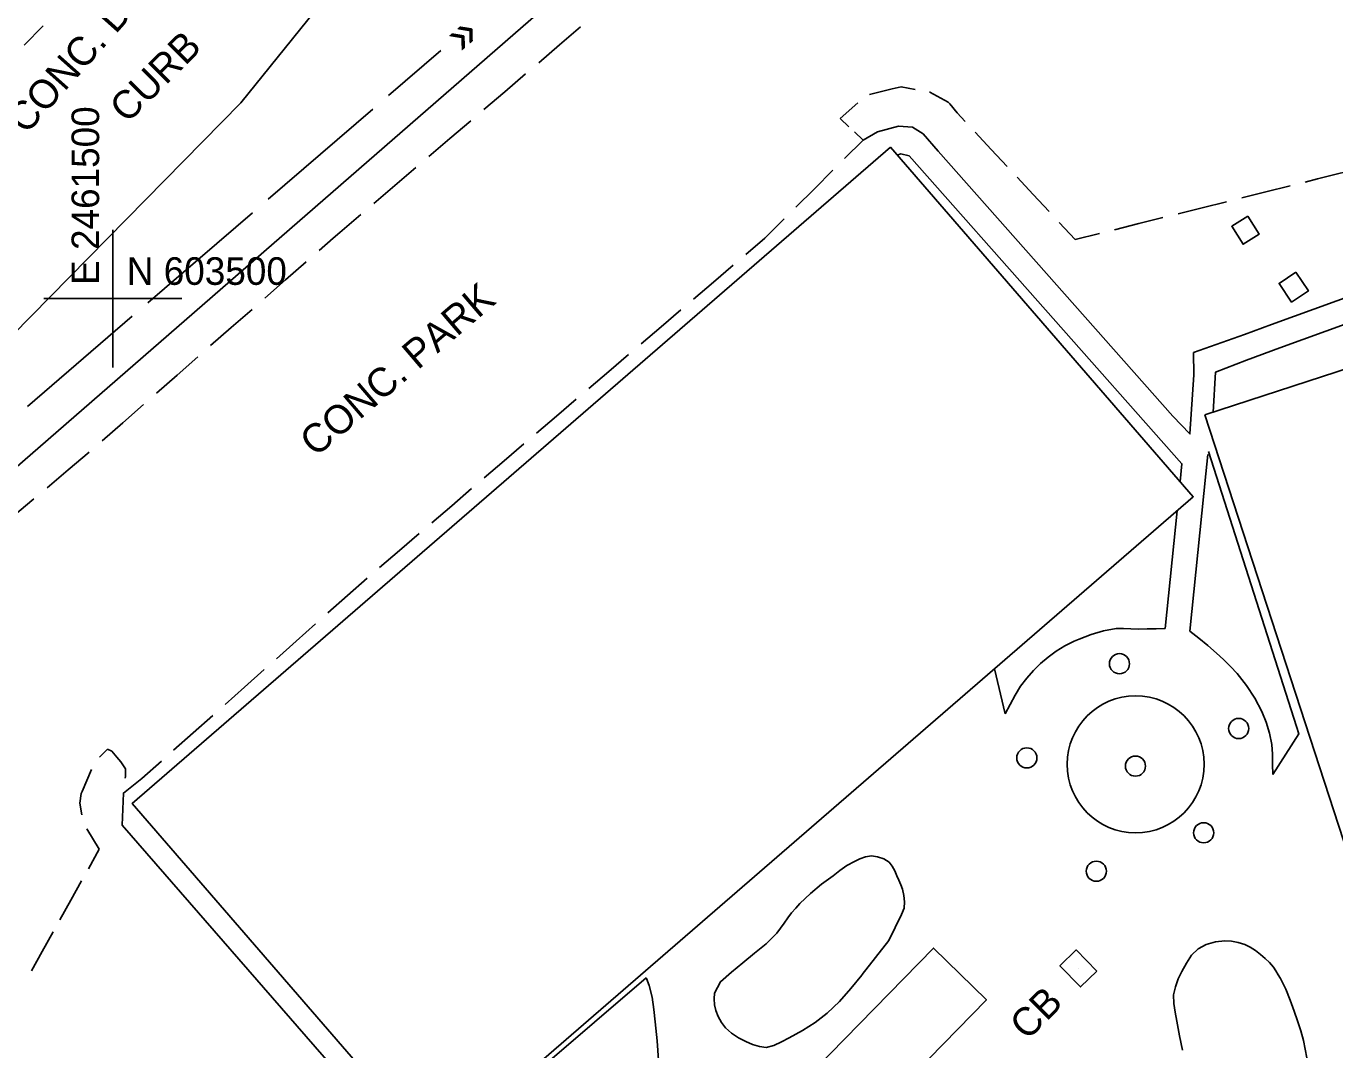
# Model space of a CAD drawing. Extents: x 2443269 to 2494951, y 591171 to 622130.
# Drawn here: x 2461487.4 to 2461677, y 603391.1 to 603539.5 of the extents above; entities that cross this region are included whole.
import ezdxf

# ---------------------------------------------------------------- set-up
doc = ezdxf.new("R2010")
doc.units = 0
for name, color, linetype in [('SURVEY - CONTROL - Grid', 7, 'Continuous'), ('SURVEY - CONTROL - Grid Text', 7, 'Continuous'), ('SURVEY - DRAINAGE - Bridge Deck with Text', 7, 'Continuous'), ('SURVEY - DRAINAGE - Storm Sewer', 7, 'Continuous'), ('SURVEY - NON-TRANSPORTATION - Buildings', 7, 'Continuous'), ('SURVEY - NON-TRANSPORTATION - Features', 7, 'Continuous'), ('SURVEY - PROPERTY - ROW Lines', 7, 'Continuous'), ('SURVEY - TRANSPORTATION - Features', 7, 'Continuous'), ('SURVEY - TRANSPORTATION - Features Text', 7, 'Continuous'), ('SURVEY - UTILITIES - Water with Text', 7, 'Continuous')]:
    doc.layers.add(name, color=color, linetype=linetype)

msp = doc.modelspace()

# ---------------------------------------------------------------- linework, layer by layer
at = {"layer": 'SURVEY - CONTROL - Grid'}
for p, q in [((2461500, 603490), (2461500, 603510)), ((2461490, 603500), (2461510, 603500))]:
    msp.add_line(p, q, dxfattribs=at)
at = {"layer": 'SURVEY - DRAINAGE - Storm Sewer'}
msp.add_line((2461639.853, 603402.914), (2461639.853, 603402.914), dxfattribs=at)
msp.add_lwpolyline([(2461642.516, 603402.529), (2461640.164, 603400.242), (2461637.19, 603403.3), (2461639.542, 603405.587)], close=True, dxfattribs=at)
at = {"layer": 'SURVEY - NON-TRANSPORTATION - Buildings'}
for points in [[(2461612.639, 603521.94), (2461656.503, 603471.28), (2461546.635, 603376.153), (2461502.77, 603426.812)], [(2461658.18, 603483.15), (2461721.926, 603503.918), (2461766.956, 603365.693), (2461703.209, 603344.926)]]:
    msp.add_lwpolyline(points, close=True, dxfattribs=at)
at = {"layer": 'SURVEY - NON-TRANSPORTATION - Features'}
for p, q in [((2461658.331, 603474.591), (2461658.619, 603477.412)), ((2461656.005, 603451.822), (2461658.331, 603474.591)), ((2461652.415, 603452.193), (2461654.171, 603469.259)), ((2461627.717, 603446.356), (2461629.246, 603439.84))]:
    msp.add_line(p, q, dxfattribs=at)
for points in [[(2461653.564, 603482.99), (2461619.561, 603521.398), (2461617.356, 603523.885), (2461615.821, 603524.847), (2461613.826, 603524.994), (2461610.782, 603524.2), (2461608.672, 603522.977)], [(2461654.604, 603473.475), (2461654.869, 603476.067), (2461615.345, 603520.719), (2461614.122, 603521.001), (2461613.606, 603520.821)], [(2461723.57, 603516.461), (2461667.822, 603496.241), (2461663.905, 603494.797), (2461656.553, 603492.173), (2461656.575, 603488.958)], [(2461725.151, 603513.193), (2461669.062, 603492.852), (2461664.223, 603491.07)], [(2461659.39, 603483.544), (2461659.712, 603489.341), (2461664.223, 603491.07)], [(2461656.575, 603488.958), (2461656.031, 603480.391), (2461653.564, 603482.99)], [(2461668.016, 603431.041), (2461671.818, 603436.91), (2461671.461, 603437.973), (2461658.695, 603477.839)], [(2461629.246, 603439.84), (2461629.968, 603441.185), (2461630.686, 603442.53), (2461631.494, 603443.817), (2461632.376, 603444.978), (2461633.337, 603446.084), (2461634.371, 603447.107), (2461635.473, 603448.049), (2461636.648, 603448.912), (2461637.881, 603449.67), (2461638.564, 603450.024), (2461639.263, 603450.352), (2461639.971, 603450.654), (2461641.717, 603451.323), (2461643.511, 603451.858), (2461645.335, 603452.163), (2461646.402, 603452.189), (2461647.478, 603452.137), (2461648.554, 603452.101), (2461649.84, 603452.117), (2461651.129, 603452.156), (2461652.415, 603452.193)], [(2461656.005, 603451.822), (2461657.307, 603450.772), (2461658.61, 603449.725), (2461659.873, 603448.633), (2461660.903, 603447.681), (2461661.904, 603446.7), (2461662.848, 603445.67), (2461664.213, 603443.945), (2461665.437, 603442.104), (2461666.441, 603440.162), (2461667.048, 603438.62), (2461667.53, 603437.019), (2461667.865, 603435.395), (2461667.99, 603433.954), (2461668.003, 603432.498), (2461668.016, 603431.041)], [(2461532.875, 603387.435), (2461501.33, 603423.698), (2461501.543, 603428.318)], [(2461601.749, 603388.315), (2461618.875, 603405.854), (2461626.53, 603398.38), (2461609.824, 603381.267)], [(2461654.945, 603391.061), (2461654.509, 603393.161), (2461654.138, 603395.273), (2461653.895, 603396.55), (2461653.679, 603397.829), (2461653.662, 603399.086), (2461653.915, 603400.244), (2461654.341, 603401.386), (2461654.863, 603402.478), (2461655.506, 603403.695), (2461656.267, 603404.853), (2461657.199, 603405.772), (2461658.37, 603406.395), (2461659.709, 603406.786), (2461661.06, 603406.927), (2461662.038, 603406.868), (2461663.022, 603406.674), (2461663.961, 603406.366), (2461664.768, 603405.975), (2461665.539, 603405.49), (2461666.264, 603404.945), (2461666.927, 603404.374), (2461667.547, 603403.748), (2461668.111, 603403.078), (2461668.482, 603402.55), (2461668.823, 603401.999), (2461669.144, 603401.438), (2461669.896, 603399.909), (2461670.526, 603398.318), (2461671.11, 603396.71), (2461671.615, 603395.303), (2461672.087, 603393.879), (2461672.491, 603392.442), (2461672.95, 603389.962)], [(2461577.258, 603401.533), (2461547.622, 603376.123), (2461563.712, 603337.754)], [(2461563.712, 603337.754), (2461565.45, 603339.745), (2461567.189, 603341.737), (2461568.83, 603343.8), (2461570.749, 603346.605), (2461572.507, 603349.529), (2461574.141, 603352.518), (2461575.378, 603354.867), (2461576.536, 603357.258), (2461577.494, 603359.706), (2461578.439, 603364.033), (2461578.807, 603368.521), (2461579.02, 603373.023), (2461579.22, 603377.609), (2461579.259, 603382.209), (2461579.148, 603386.802), (2461579.026, 603389.604), (2461578.846, 603392.403), (2461578.561, 603395.191), (2461578.357, 603396.966), (2461578.108, 603398.735), (2461577.685, 603400.454), (2461577.294, 603401.451), (2461577.258, 603401.533)]]:
    msp.add_lwpolyline(points, dxfattribs=at)
for points in [[(2461664.39, 603511.956), (2461666.037, 603509.332), (2461663.728, 603507.881), (2461662.081, 603510.506)], [(2461671.369, 603503.846), (2461673.19, 603501.133), (2461670.752, 603499.499), (2461668.931, 603502.212)], [(2461612.379, 603406.963), (2461608.56, 603402.022), (2461608.488, 603401.953), (2461606.891, 603400.024), (2461605.253, 603398.128), (2461603.465, 603396.409), (2461601.733, 603395.086), (2461599.883, 603393.899), (2461597.957, 603392.859), (2461596.871, 603392.271), (2461595.762, 603391.73), (2461594.637, 603391.474), (2461593.649, 603391.586), (2461592.648, 603391.901), (2461591.694, 603392.311), (2461590.627, 603392.855), (2461589.62, 603393.521), (2461588.757, 603394.322), (2461588.167, 603395.083), (2461587.671, 603395.933), (2461587.324, 603396.825), (2461587.153, 603397.649), (2461587.094, 603398.505), (2461587.156, 603399.319), (2461588.039, 603400.975), (2461589.63, 603402.38), (2461591.267, 603403.735), (2461592.934, 603405.142), (2461594.653, 603406.494), (2461596.192, 603408.013), (2461596.723, 603408.735), (2461597.225, 603409.489), (2461597.747, 603410.224), (2461598.321, 603410.949), (2461598.915, 603411.658), (2461599.532, 603412.344), (2461601.031, 603413.784), (2461602.645, 603415.103), (2461604.318, 603416.349), (2461605.319, 603417.097), (2461606.336, 603417.816), (2461607.415, 603418.416), (2461608.216, 603418.781), (2461609.043, 603419.089), (2461609.87, 603419.217), (2461610.782, 603419.105), (2461611.687, 603418.787), (2461612.448, 603418.295), (2461612.898, 603417.727), (2461613.249, 603417.042), (2461613.57, 603416.34), (2461613.875, 603415.7), (2461614.154, 603415.05), (2461614.374, 603414.384), (2461614.571, 603413.485), (2461614.673, 603412.56), (2461614.63, 603411.664), (2461614.23, 603410.749)]]:
    msp.add_lwpolyline(points, close=True, dxfattribs=at)
for centre, radius in [((2461645.814, 603447.083), 1.458), ((2461648.158, 603432.498), 9.925), ((2461663.087, 603437.69), 1.458), ((2461632.398, 603433.425), 1.458), ((2461648.133, 603432.244), 1.458), ((2461658.012, 603422.578), 1.458), ((2461642.464, 603417.001), 1.458)]:
    msp.add_circle(centre, radius, dxfattribs=at)
at = {"layer": 'SURVEY - PROPERTY - ROW Lines'}
msp.add_line((2461375.36, 603379.221), (2461715.661, 603675.652), dxfattribs=at)
at = {"layer": 'SURVEY - TRANSPORTATION - Features'}
for p, q in [((2461487.139, 603536.76), (2461489.898, 603539.526)), ((2461567.746, 603539.386), (2461564.715, 603536.797)), ((2461564.715, 603536.797), (2461561.684, 603534.207)), ((2461559.789, 603532.589), (2461556.758, 603530)), ((2461612.894, 603530.412), (2461614.197, 603530.726)), ((2461614.197, 603530.726), (2461616.219, 603530.337)), ((2461556.758, 603530), (2461553.727, 603527.411)), ((2461609.588, 603529.615), (2461612.894, 603530.412)), ((2461618.306, 603529.936), (2461618.328, 603529.932)), ((2461618.328, 603529.932), (2461621.008, 603528.475)), ((2461605.375, 603526.12), (2461607.903, 603528.393)), ((2461621.008, 603528.475), (2461621.218, 603528.223)), ((2461621.218, 603528.223), (2461622.297, 603526.927)), ((2461622.297, 603526.927), (2461623.465, 603525.673)), ((2461551.833, 603525.793), (2461548.801, 603523.203)), ((2461606.631, 603524.922), (2461605.375, 603526.12)), ((2461605.375, 603526.12), (2461605.375, 603526.12)), ((2461548.801, 603523.203), (2461545.77, 603520.614)), ((2461608.672, 603522.977), (2461607.416, 603524.174)), ((2461624.914, 603524.119), (2461627.232, 603521.631)), ((2461605.983, 603520.293), (2461608.672, 603522.977)), ((2461608.672, 603522.977), (2461608.672, 603522.977)), ((2461627.232, 603521.631), (2461629.549, 603519.143)), ((2461543.876, 603518.996), (2461540.845, 603516.407)), ((2461601.612, 603515.931), (2461604.302, 603518.615)), ((2461630.998, 603517.588), (2461633.316, 603515.101)), ((2461674.492, 603517.35), (2461676.238, 603517.783)), ((2461676.238, 603517.783), (2461679.748, 603518.653)), ((2461540.845, 603516.407), (2461537.813, 603513.817)), ((2461598.923, 603513.248), (2461601.612, 603515.931)), ((2461663.52, 603514.605), (2461667.028, 603515.482)), ((2461667.028, 603515.482), (2461670.536, 603516.36)), ((2461672.729, 603516.909), (2461674.492, 603517.35)), ((2461633.316, 603515.101), (2461635.634, 603512.613)), ((2461657.819, 603513.178), (2461661.327, 603514.056)), ((2461535.919, 603512.199), (2461532.888, 603509.61)), ((2461648.61, 603510.874), (2461652.118, 603511.752)), ((2461654.31, 603512.301), (2461657.819, 603513.178)), ((2461594.553, 603508.886), (2461597.242, 603511.57)), ((2461637.082, 603511.058), (2461639.4, 603508.57)), ((2461645.101, 603509.997), (2461648.61, 603510.874)), ((2461531.92, 603508.784), (2461529.88, 603506.993)), ((2461532.888, 603509.61), (2461531.92, 603508.784)), ((2461591.672, 603506.41), (2461594.456, 603508.79)), ((2461594.456, 603508.79), (2461594.553, 603508.886)), ((2461639.4, 603508.57), (2461642.909, 603509.448)), ((2461639.4, 603508.57), (2461639.4, 603508.57)), ((2461528.008, 603505.35), (2461525.012, 603502.72)), ((2461586.979, 603502.398), (2461589.867, 603504.867)), ((2461525.012, 603502.72), (2461522.016, 603500.09)), ((2461584.091, 603499.928), (2461586.979, 603502.398)), ((2461520.143, 603498.447), (2461517.147, 603495.817)), ((2461579.398, 603495.916), (2461582.286, 603498.385)), ((2461517.147, 603495.817), (2461514.151, 603493.187)), ((2461576.511, 603493.447), (2461579.398, 603495.916)), ((2461512.278, 603491.544), (2461509.282, 603488.914)), ((2461571.818, 603489.435), (2461574.706, 603491.904)), ((2461568.93, 603486.966), (2461571.818, 603489.435)), ((2461509.282, 603488.914), (2461506.286, 603486.285)), ((2461564.237, 603482.954), (2461567.125, 603485.423)), ((2461504.413, 603484.641), (2461501.417, 603482.011)), ((2461501.417, 603482.011), (2461498.421, 603479.382)), ((2461561.349, 603480.485), (2461564.237, 603482.954)), ((2461496.538, 603477.75), (2461493.497, 603475.173)), ((2461556.657, 603476.473), (2461559.544, 603478.942)), ((2461553.769, 603474.004), (2461556.657, 603476.473)), ((2461493.497, 603475.173), (2461490.456, 603472.595)), ((2461549.076, 603469.991), (2461551.964, 603472.46)), ((2461488.555, 603470.984), (2461485.514, 603468.407)), ((2461546.188, 603467.522), (2461549.076, 603469.991)), ((2461541.495, 603463.51), (2461544.383, 603465.979)), ((2461538.607, 603461.041), (2461541.495, 603463.51)), ((2461533.973, 603456.962), (2461536.811, 603459.488)), ((2461531.135, 603454.436), (2461533.973, 603456.962)), ((2461526.522, 603450.332), (2461529.361, 603452.858)), ((2461523.684, 603447.806), (2461526.522, 603450.332)), ((2461519.072, 603443.701), (2461521.91, 603446.227)), ((2461516.234, 603441.176), (2461519.072, 603443.701)), ((2461511.621, 603437.071), (2461514.46, 603439.597)), ((2461508.783, 603434.545), (2461511.621, 603437.071)), ((2461498.049, 603433.538), (2461499.197, 603434.686)), ((2461499.197, 603434.686), (2461499.817, 603434.417)), ((2461499.817, 603434.417), (2461500.558, 603433.525)), ((2461500.558, 603433.525), (2461501.12, 603432.849)), ((2461501.12, 603432.849), (2461501.802, 603431.855)), ((2461504.171, 603430.441), (2461507.009, 603432.966)), ((2461495.522, 603428.562), (2461496.899, 603431.735)), ((2461501.543, 603428.318), (2461504.171, 603430.441)), ((2461501.796, 603430.716), (2461501.751, 603430.485)), ((2461501.802, 603431.855), (2461501.796, 603430.716)), ((2461504.171, 603430.441), (2461504.171, 603430.441)), ((2461495.395, 603428.269), (2461495.522, 603428.562)), ((2461501.504, 603428.388), (2461501.543, 603428.318)), ((2461495.188, 603426.868), (2461495.395, 603428.269)), ((2461495.494, 603425.173), (2461495.188, 603426.868)), ((2461498.01, 603420.195), (2461496.195, 603423.139)), ((2461496.437, 603417.371), (2461498.01, 603420.195)), ((2461498.01, 603420.195), (2461498.01, 603420.195)), ((2461493.882, 603412.784), (2461495.455, 603415.607)), ((2461492.31, 603409.961), (2461493.882, 603412.784)), ((2461489.755, 603405.373), (2461491.327, 603408.196)), ((2461488.183, 603402.55), (2461489.755, 603405.373))]:
    msp.add_line(p, q, dxfattribs=at)
msp.add_lwpolyline([(2461649.779, 603757.801), (2461631.937, 603735.022), (2461614.154, 603706.121), (2461575.091, 603670.977), (2461535.653, 603636.612), (2461533.455, 603633.675), (2461532.727, 603629.813), (2461530.92, 603619.138), (2461526.657, 603590.701), (2461530.981, 603583.26), (2461535.255, 603564.77), (2461530.252, 603542.945), (2461518.515, 603528.392), (2461485.399, 603494.67), (2461449.744, 603458.915), (2461432.06, 603441.012)], dxfattribs=at)
at = {"layer": 'SURVEY - UTILITIES - Water with Text'}
for p, q in [((2461539.901, 603529.426), (2461547.477, 603535.953)), ((2461522.475, 603514.414), (2461537.628, 603527.468)), ((2461512.626, 603505.929), (2461520.203, 603512.456)), ((2461505.05, 603499.402), (2461512.626, 603505.929)), ((2461487.625, 603484.39), (2461502.777, 603497.444))]:
    msp.add_line(p, q, dxfattribs=at)

# ---------------------------------------------------------------- texts
at = {"layer": 'SURVEY - CONTROL - Grid Text'}
msp.add_text('E 2461500', height=4, rotation=90, dxfattribs=at).set_placement((2461498, 603502))
msp.add_text('N 603500', height=4, dxfattribs=at).set_placement((2461502, 603502))
at = {"layer": 'SURVEY - DRAINAGE - Bridge Deck with Text'}
msp.add_text('CB', height=4.101, rotation=45, dxfattribs=at).set_placement((2461632.442, 603392.35))
at = {"layer": 'SURVEY - TRANSPORTATION - Features Text'}
for s, height, rotation, p in [('CONC. DR.', 4.166, 48.35806, (2461487.423, 603523.682)), ('CURB', 4.101, 44.9, (2461502.04, 603525.287)), ('CONC. PARK', 4.166, 40.50361, (2461529.348, 603476.926))]:
    msp.add_text(s, height=height, rotation=rotation, dxfattribs=at).set_placement(p)
at = {"layer": 'SURVEY - UTILITIES - Water with Text'}
msp.add_text('»', height=5, rotation=40.74541, dxfattribs=at).set_placement((2461550.687, 603535.419))

doc.saveas('drawing.dxf')
